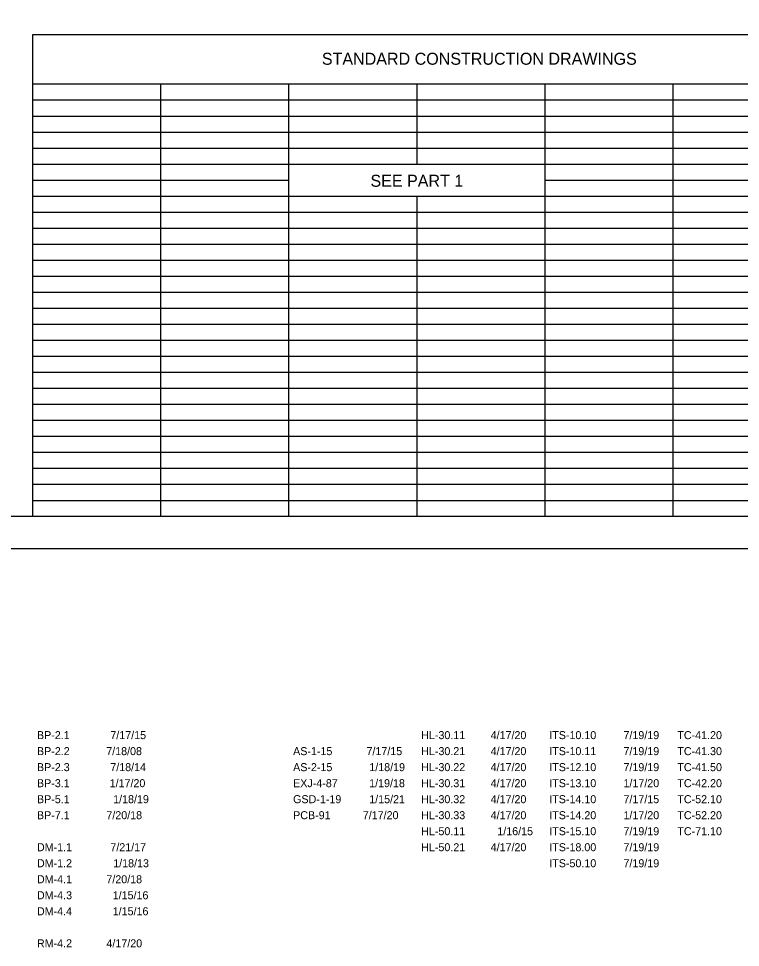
# Model space of a CAD drawing. Extents: x 0 to 34, y -6.2 to 22.
# Drawn here: x 10.94 to 22.21, y -6.23 to 8.27 of the extents above; entities that cross this region are included whole.
import ezdxf

# ---------------------------------------------------------------- set-up
doc = ezdxf.new("R2010")
doc.units = 0
for name, color, linetype in [('SH_Border', 7, 'Continuous'), ('SH_Cut_Line', 7, 'Continuous'), ('SH_Data', 7, 'Continuous')]:
    doc.layers.add(name, color=color, linetype=linetype)

msp = doc.modelspace()

# ---------------------------------------------------------------- linework, layer by layer
at = {"layer": 'SH_Border'}
msp.add_lwpolyline([(2, 21.5), (33.5, 21.5), (33.5, 0.5), (2, 0.5)], close=True, dxfattribs=at)
at = {"layer": 'SH_Cut_Line'}
msp.add_lwpolyline([(0, 0), (34, 0), (34, 22), (0, 22)], close=True, dxfattribs=at)
at = {"layer": 'SH_Data'}
for p, q in [((11.159, 8.021), (25.266, 8.021)), ((11.159, 0.5), (11.159, 8.021)), ((11.159, 7.25), (25.266, 7.25)), ((11.159, 7.25), (25.266, 7.25)), ((13.159, 0.5), (13.159, 7.25)), ((15.159, 6.25), (15.159, 7.25)), ((17.159, 6.75), (17.159, 7.25)), ((19.159, 6.25), (19.159, 7.25)), ((21.159, 0.5), (21.159, 7.25)), ((11.159, 7), (25.266, 7)), ((11.159, 6.75), (25.266, 6.75)), ((17.159, 6), (17.159, 6.75)), ((11.159, 6.5), (19.159, 6.5)), ((19.159, 6.5), (25.266, 6.5)), ((11.159, 6.25), (25.266, 6.25)), ((15.159, 0.5), (15.159, 6.25)), ((19.159, 0.5), (19.159, 6.25)), ((11.159, 6), (25.266, 6)), ((11.159, 5.75), (15.159, 5.75)), ((19.159, 5.75), (23.159, 5.75)), ((11.159, 5.5), (25.266, 5.5)), ((17.159, 0.5), (17.159, 5.5)), ((11.159, 5.25), (25.266, 5.25)), ((11.159, 5), (25.266, 5)), ((11.159, 4.75), (23.159, 4.75)), ((11.159, 4.75), (25.266, 4.75)), ((11.159, 4.5), (23.159, 4.5)), ((11.159, 4.5), (25.266, 4.5)), ((11.159, 4.25), (23.159, 4.25)), ((11.159, 4), (23.159, 4)), ((11.159, 3.75), (23.159, 3.75)), ((11.159, 3.5), (25.266, 3.5)), ((11.159, 3.25), (23.159, 3.25)), ((11.159, 3), (25.266, 3)), ((11.159, 2.75), (23.159, 2.75)), ((11.159, 2.5), (25.266, 2.5)), ((11.159, 2.25), (23.159, 2.25)), ((11.159, 2), (25.266, 2)), ((11.159, 1.75), (23.159, 1.75)), ((11.159, 1.5), (25.266, 1.5)), ((11.159, 1.25), (23.159, 1.25)), ((11.159, 1), (25.266, 1)), ((11.159, 0.75), (23.159, 0.75))]:
    msp.add_line(p, q, dxfattribs=at)

# ---------------------------------------------------------------- texts
for s, height, p in [('STANDARD CONSTRUCTION DRAWINGS', 0.1875, (15.673, 7.55)), ('SEE PART 1', 0.1875, (16.432, 5.645)), ('BP-2.1', 0.125, (11.224, -2.978)), ('7/17/15', 0.125, (12.37, -2.978)), ('HL-30.11', 0.125, (17.224, -2.978)), ('4/17/20', 0.125, (18.309, -2.978)), ('ITS-10.10', 0.125, (19.224, -2.978)), ('7/19/19', 0.125, (20.383, -2.978)), ('TC-41.20', 0.125, (21.224, -2.978)), ('BP-2.2', 0.125, (11.224, -3.228)), ('7/18/08', 0.125, (12.306, -3.228)), ('AS-1-15', 0.125, (15.224, -3.228)), ('7/17/15', 0.125, (16.37, -3.228)), ('HL-30.21', 0.125, (17.224, -3.228)), ('4/17/20', 0.125, (18.309, -3.228)), ('ITS-10.11', 0.125, (19.224, -3.228)), ('7/19/19', 0.125, (20.383, -3.228)), ('TC-41.30', 0.125, (21.224, -3.228)), ('BP-2.3', 0.125, (11.224, -3.478)), ('7/18/14', 0.125, (12.369, -3.478)), ('AS-2-15', 0.125, (15.224, -3.478)), ('1/18/19', 0.125, (16.414, -3.478)), ('HL-30.22', 0.125, (17.224, -3.478)), ('4/17/20', 0.125, (18.309, -3.478)), ('ITS-12.10', 0.125, (19.224, -3.478)), ('7/19/19', 0.125, (20.383, -3.478)), ('TC-41.50', 0.125, (21.224, -3.478)), ('BP-3.1', 0.125, (11.224, -3.728)), ('1/17/20', 0.125, (12.359, -3.728)), ('EXJ-4-87', 0.125, (15.224, -3.728)), ('1/19/18', 0.125, (16.412, -3.728)), ('HL-30.31', 0.125, (17.224, -3.728)), ('4/17/20', 0.125, (18.309, -3.728)), ('ITS-13.10', 0.125, (19.224, -3.728)), ('1/17/20', 0.125, (20.383, -3.728)), ('TC-42.20', 0.125, (21.224, -3.728)), ('BP-5.1', 0.125, (11.224, -3.978)), ('1/18/19', 0.125, (12.414, -3.978)), ('GSD-1-19', 0.125, (15.224, -3.978)), ('1/15/21', 0.125, (16.413, -3.978)), ('HL-30.32', 0.125, (17.224, -3.978)), ('4/17/20', 0.125, (18.309, -3.978)), ('ITS-14.10', 0.125, (19.224, -3.978)), ('7/17/15', 0.125, (20.383, -3.978)), ('TC-52.10', 0.125, (21.224, -3.978)), ('BP-7.1', 0.125, (11.224, -4.228)), ('7/20/18', 0.125, (12.308, -4.228)), ('PCB-91', 0.125, (15.224, -4.228)), ('7/17/20', 0.125, (16.312, -4.228)), ('HL-30.33', 0.125, (17.224, -4.228)), ('4/17/20', 0.125, (18.309, -4.228)), ('ITS-14.20', 0.125, (19.224, -4.228)), ('1/17/20', 0.125, (20.383, -4.228)), ('TC-52.20', 0.125, (21.224, -4.228)), ('1/16/15', 0.125, (18.413, -4.478)), ('7/19/19', 0.125, (20.383, -4.478)), ('HL-50.11', 0.125, (17.224, -4.478)), ('ITS-15.10', 0.125, (19.224, -4.478)), ('TC-71.10', 0.125, (21.224, -4.478)), ('DM-1.1', 0.125, (11.224, -4.728)), ('7/21/17', 0.125, (12.37, -4.728)), ('HL-50.21', 0.125, (17.224, -4.728)), ('4/17/20', 0.125, (18.309, -4.728)), ('ITS-18.00', 0.125, (19.224, -4.728)), ('7/19/19', 0.125, (20.383, -4.728)), ('DM-1.2', 0.125, (11.224, -4.978)), ('1/18/13', 0.125, (12.415, -4.978)), ('ITS-50.10', 0.125, (19.224, -4.978)), ('7/19/19', 0.125, (20.383, -4.978)), ('DM-4.1', 0.125, (11.224, -5.228)), ('7/20/18', 0.125, (12.308, -5.228)), ('DM-4.3', 0.125, (11.224, -5.478)), ('1/15/16', 0.125, (12.407, -5.478)), ('DM-4.4', 0.125, (11.224, -5.728)), ('1/15/16', 0.125, (12.407, -5.728)), ('RM-4.2', 0.125, (11.224, -6.228)), ('4/17/20', 0.125, (12.309, -6.228))]:
    msp.add_text(s, height=height, dxfattribs=at).set_placement(p)

doc.saveas('drawing.dxf')
